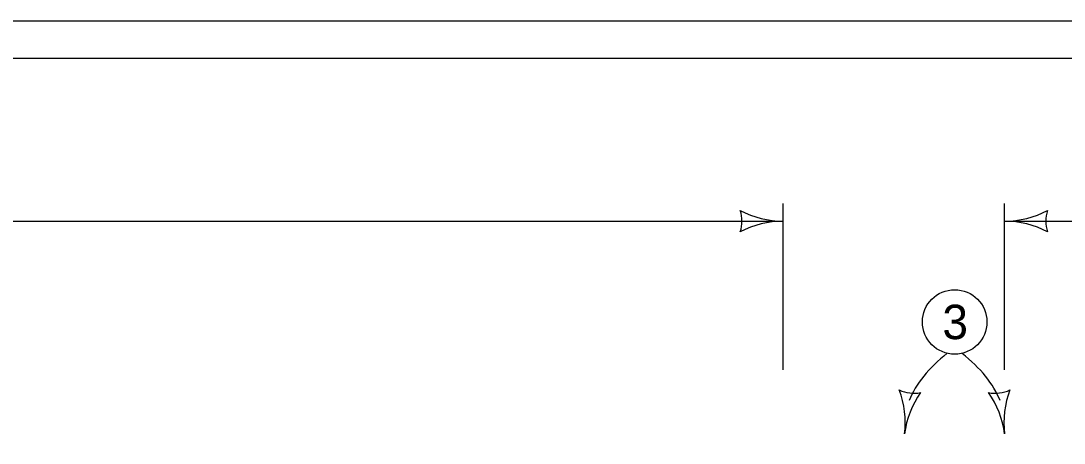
# Model space of a CAD drawing. Extents: x 10038 to 81668, y 7924 to 11018.
# Drawn here: x 11041.5 to 11526.6, y 9747.6 to 9944 of the extents above; entities that cross this region are included whole.
import ezdxf

# ---------------------------------------------------------------- set-up
doc = ezdxf.new("R2010")
doc.units = 0
for name, color, linetype in [('DsnShtMinorGrid05', 7, 'Continuous'), ('DsnShtMinorGrid06', 7, 'Continuous'), ('DsnShtMinorGrid09', 7, 'Continuous'), ('SheetBorder', 7, 'Continuous')]:
    doc.layers.add(name, color=color, linetype=linetype)

msp = doc.modelspace()

# ---------------------------------------------------------------- linework, layer by layer
at = {"layer": 'DsnShtMinorGrid05'}
for p, q in [((11396.01, 9781.65), (11396.01, 9859.05)), ((11498.9, 9781.65), (11498.9, 9859.05)), ((10373.6, 9850.84), (11396.01, 9850.84)), ((11498.9, 9850.84), (11634.9, 9850.84))]:
    msp.add_line(p, q, dxfattribs=at)
for centre, radius, start, end in [((11360.38, 9850.84), 16.42, 342.2666, 17.7333), ((11396.01, 9893.34), 42.5, 241.9275, 270), ((11498.9, 9893.34), 42.5, 270, 298.0725), ((11534.53, 9850.84), 16.42, 162.2666, 197.7334), ((11396.01, 9808.34), 42.5, 90, 118.0725), ((11498.9, 9808.34), 42.5, 61.9275, 90)]:
    msp.add_arc(centre, radius, start, end, dxfattribs=at)
at = {"layer": 'DsnShtMinorGrid06'}
msp.add_line((10150.33, 9926.71), (13246.02, 9926.71), dxfattribs=at)
at = {"layer": 'DsnShtMinorGrid09'}
msp.add_circle((11475.7, 9803.97), 15, dxfattribs=at)
for centre, radius, start, end in [((11456.81, 9787.22), 16.42, 245.1764, 280.6431), ((11410.24, 9757.11), 42.5, 352.9098, 20.9823), ((11494.59, 9746.61), 42.5, 144.8373, 172.9098), ((11494.5, 9787.22), 16.42, 259.3569, 294.8236), ((11456.72, 9746.61), 42.5, 7.0902, 35.1627), ((11541.07, 9757.11), 42.5, 159.0177, 187.0902)]:
    msp.add_arc(centre, radius, start, end, dxfattribs=at)
for centre, major_axis, start_param, end_param in [((11541.56, 9764.2), (-89.15, -12.34), 5.523141, 5.97728), ((11409.75, 9764.2), (89.15, -12.34), 0.305948, 0.759638)]:
    msp.add_ellipse(centre, major_axis=major_axis, ratio=0.555556, start_param=start_param, end_param=end_param, dxfattribs=at)
at = {"layer": 'SheetBorder'}
msp.add_lwpolyline([(10132.52, 9944.02), (13267.53, 9944.02), (13267.53, 7924.02), (10132.52, 7924.02)], close=True, dxfattribs=at)

# ---------------------------------------------------------------- texts
at = {"layer": 'DsnShtMinorGrid09'}
msp.add_text('3', height=16, dxfattribs=at).set_placement((11470, 9795.97))

doc.saveas('drawing.dxf')
